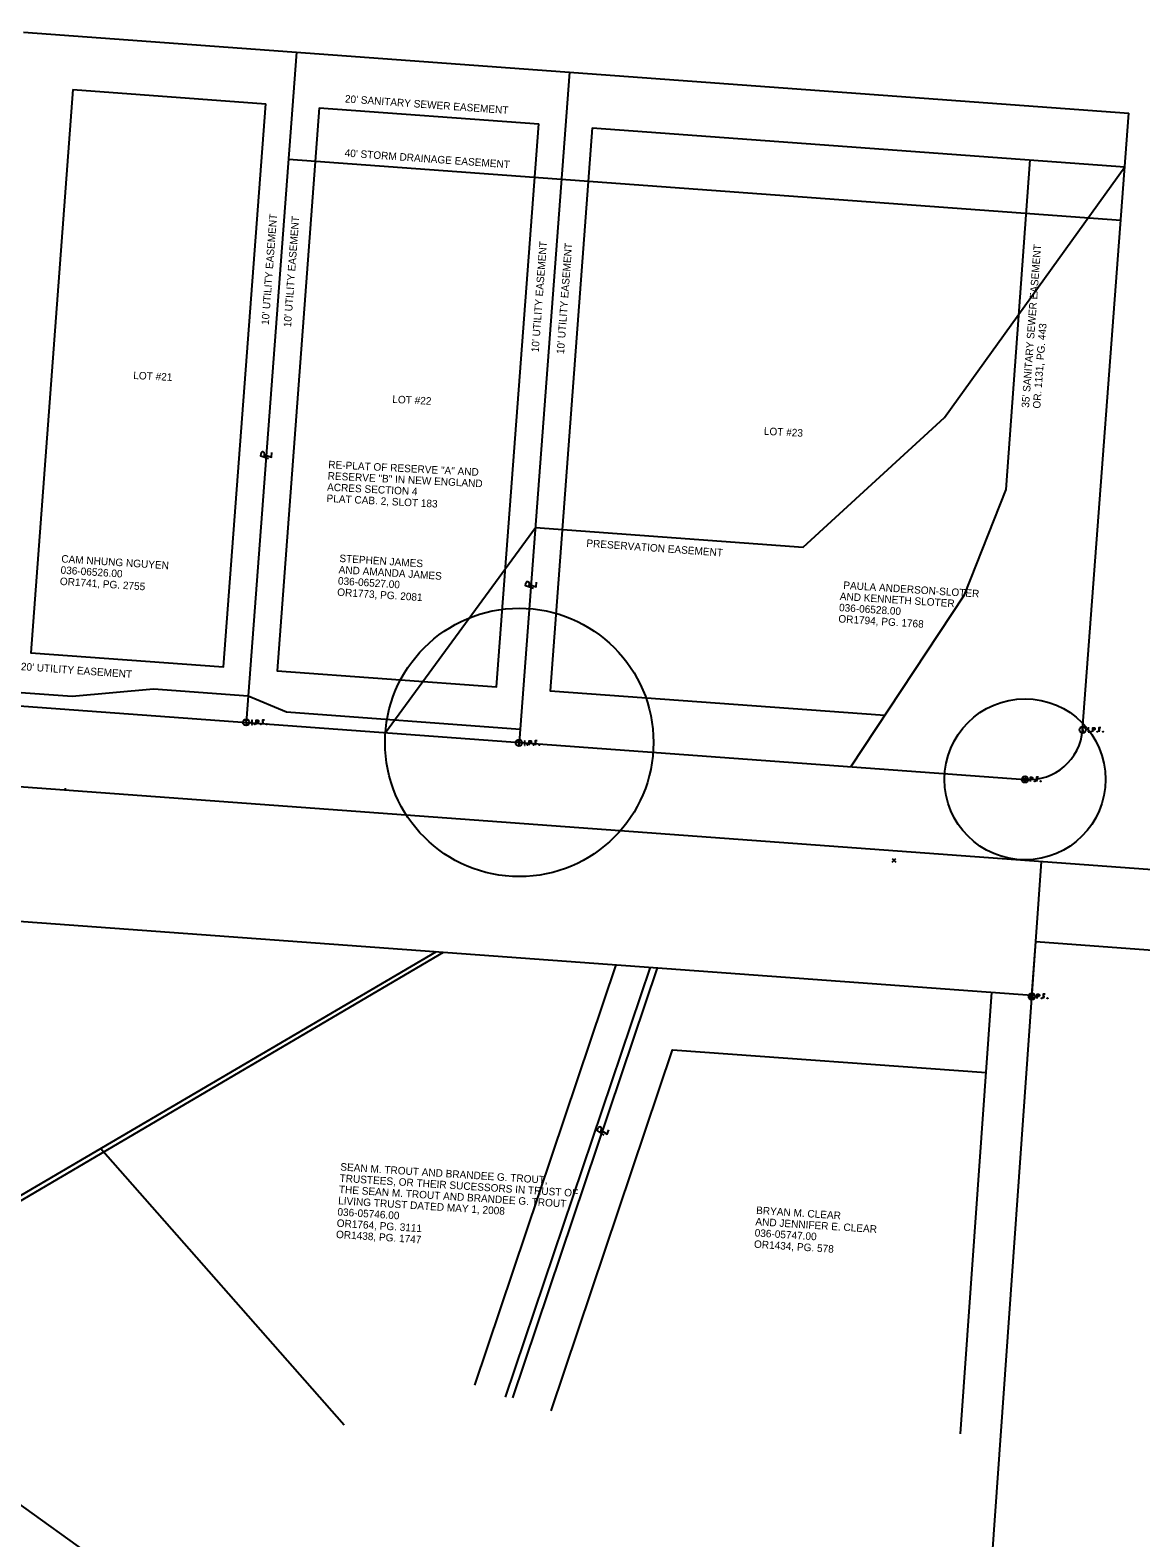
# Model space of a CAD drawing. Extents: x 1898254 to 1901377, y 701554 to 704886.
# Drawn here: x 1900233 to 1900647, y 702920 to 703481 of the extents above; entities that cross this region are included whole.
import ezdxf

# ---------------------------------------------------------------- set-up
doc = ezdxf.new("R2010")
doc.units = 0
for name, color, linetype in [('_CIVIL_CONSTRUCTION', 7, 'Continuous'), ('DV_X_Property_Line', 7, 'Continuous'), ('DV_X_Text', 7, 'Continuous'), ('RW_X_CL', 7, 'Continuous'), ('RW_X_Esmt_SC', 7, 'Continuous'), ('RW_X_Esmt_SH', 7, 'Continuous'), ('RW_X_Esmt_SW', 7, 'Continuous'), ('RW_X_Esmt_U', 7, 'Continuous'), ('RW_X_Fee_RW', 7, 'Continuous'), ('SC_Scratch1', 7, 'Continuous'), ('SC_Scratch2', 7, 'Continuous'), ('SC_Scratch3', 7, 'Continuous'), ('SC_Scratch5', 7, 'Continuous'), ('SC_Scratch6', 7, 'Continuous'), ('SC_Scratch9', 7, 'Continuous'), ('SV_X_Mon_Cells_Found', 7, 'Continuous'), ('SV_X_Random_Point', 7, 'Continuous')]:
    doc.layers.add(name, color=color, linetype=linetype)

msp = doc.modelspace()

# ---------------------------------------------------------------- linework, layer by layer
at = {"layer": '_CIVIL_CONSTRUCTION'}
msp.add_lwpolyline([(1900212.15, 703230.94), (1900212.52, 703235.93), (1900249.06, 703233.26), (1900279.35, 703236.06), (1900314.63, 703233.48), (1900328.85, 703227.43), (1900415.98, 703221.06), (1900415.61, 703216.07)], dxfattribs=at)
at = {"layer": 'DV_X_Property_Line'}
for p, q in [((1900230.87, 703480.71), (1900642.66, 703450.49)), ((1900332.6, 703473.25), (1900313.88, 703223.51)), ((1900434.32, 703465.78), (1900415.61, 703216.07)), ((1900320.66, 703322.28), (1900320.75, 703323.57)), ((1900321.34, 703323.03), (1900321.34, 703323.03)), ((1900419.32, 703273.94), (1900419.42, 703275.23)), ((1900420, 703274.69), (1900420, 703274.69)), ((1900246.51, 703198.35), (1900246.57, 703199.08)), ((1900573.07, 702649.15), (1900610.16, 703171.77)), ((1900445.82, 703070.67), (1900446.23, 703071.9)), ((1900446.67, 703071.23), (1900446.67, 703071.23))]:
    msp.add_line(p, q, dxfattribs=at)
for points in [[(1900322.21, 703321.74), (1900319.31, 703322.74), (1900319.39, 703323.77)], [(1900320.4, 703323.37), (1900323.29, 703322.36), (1900323.42, 703324.1)], [(1900420.87, 703273.4), (1900417.98, 703274.4), (1900418.06, 703275.43)], [(1900419.06, 703275.03), (1900421.95, 703274.02), (1900422.08, 703275.76)], [(1900447.2, 703069.76), (1900444.63, 703071.45), (1900444.97, 703072.43)], [(1900445.84, 703071.79), (1900448.39, 703070.1), (1900448.95, 703071.75)]]:
    msp.add_lwpolyline(points, dxfattribs=at)
for centre, start, end in [((1900320.06, 703323.62), 356.1849, 167.042), ((1900418.73, 703275.28), 356.1849, 167.042), ((1900445.58, 703072.11), 341.8852, 152.7423)]:
    msp.add_arc(centre, 0.69, start, end, dxfattribs=at)
at = {"layer": 'RW_X_CL'}
msp.add_line((1899815.76, 703229.84), (1901162.17, 703131.42), dxfattribs=at)
at = {"layer": 'RW_X_Esmt_SC'}
msp.add_lwpolyline([(1900365.74, 703219.72), (1900421.6, 703296.1), (1900521.34, 703288.81), (1900574.06, 703337.18), (1900641.2, 703430.54)], dxfattribs=at)
at = {"layer": 'RW_X_Esmt_SH'}
msp.add_line((1900608.03, 703141.85), (1901159.98, 703101.5), dxfattribs=at)
at = {"layer": 'RW_X_Esmt_SW'}
for p, q in [((1900249.32, 703459.31), (1900321.13, 703454.03)), ((1900341.07, 703452.57), (1900422.85, 703446.57)), ((1900442.8, 703445.1), (1900641.2, 703430.54)), ((1900399.03, 702976.61), (1900451.69, 703133.22))]:
    msp.add_line(p, q, dxfattribs=at)
for points in [[(1900539.12, 703207.04), (1900581.45, 703271.1), (1900596.96, 703310.34), (1900605.93, 703433.13)], [(1900427.46, 702967.05), (1900472.71, 703101.6), (1900589.53, 703093.06)]]:
    msp.add_lwpolyline(points, dxfattribs=at)
at = {"layer": 'RW_X_Esmt_U'}
for p, q in [((1900329.61, 703433.36), (1900639.68, 703410.6)), ((1900579.98, 702958.41), (1900591.66, 703122.99))]:
    msp.add_line(p, q, dxfattribs=at)
for points in [[(1900249.32, 703459.31), (1900233.59, 703249.43), (1900305.4, 703244.18), (1900321.13, 703454.03)], [(1900341.07, 703452.57), (1900325.35, 703242.72), (1900407.13, 703236.74), (1900422.85, 703446.57)], [(1900442.8, 703445.1), (1900427.08, 703235.29), (1900551.76, 703226.17)]]:
    msp.add_lwpolyline(points, dxfattribs=at)
at = {"layer": 'RW_X_Fee_RW'}
for p, q in [((1900625.5, 703220.75), (1900642.66, 703450.49)), ((1899817.89, 703259.76), (1900604.1, 703202.29)), ((1899868.13, 703175.88), (1900606.62, 703121.9)), ((1900606.62, 703121.9), (1900608.03, 703141.85))]:
    msp.add_line(p, q, dxfattribs=at)
msp.add_arc((1900605.56, 703222.24), 20, 265.8192, 355.7289, dxfattribs=at)
at = {"layer": 'SC_Scratch1'}
msp.add_circle((1900604.03, 703202.3), 30, dxfattribs=at)
at = {"layer": 'SC_Scratch2'}
msp.add_circle((1899815.76, 703229.84), 1561.35, dxfattribs=at)
at = {"layer": 'SC_Scratch3'}
msp.add_circle((1900415.61, 703216.07), 50, dxfattribs=at)
at = {"layer": 'SC_Scratch5'}
for p, q in [((1900625.5, 703220.75), (1900642.66, 703450.49)), ((1899817.89, 703259.76), (1900604.1, 703202.29)), ((1899868.13, 703175.88), (1900606.62, 703121.9)), ((1900606.62, 703121.9), (1900608.03, 703141.85)), ((1900608.03, 703141.85), (1901159.98, 703101.5))]:
    msp.add_line(p, q, dxfattribs=at)
msp.add_lwpolyline([(1900212.15, 703230.94), (1900212.52, 703235.93), (1900249.06, 703233.26), (1900279.35, 703236.06), (1900314.63, 703233.48), (1900328.85, 703227.43), (1900415.98, 703221.06), (1900415.61, 703216.07)], dxfattribs=at)
msp.add_arc((1900605.56, 703222.24), 20, 265.8192, 355.7289, dxfattribs=at)
at = {"layer": 'SC_Scratch6'}
for p, q in [((1900144.84, 702995.46), (1900387.35, 703137.92)), ((1900413.24, 702971.83), (1900467.13, 703132.09))]:
    msp.add_line(p, q, dxfattribs=at)
at = {"layer": 'SC_Scratch9'}
for p, q in [((1900141.16, 702995.38), (1900384.72, 703138.12)), ((1900410.45, 702972.08), (1900464.51, 703132.28)), ((1900350.32, 702961.74), (1900259.61, 703064.8)), ((1900141.16, 702995.38), (1900324.05, 702864.31))]:
    msp.add_line(p, q, dxfattribs=at)
at = {"layer": 'SV_X_Mon_Cells_Found'}
for p, q in [((1900313.87, 703223.67), (1900313.87, 703222.79)), ((1900625.51, 703220.87), (1900625.51, 703219.99)), ((1900415.48, 703216.01), (1900415.48, 703215.13))]:
    msp.add_line(p, q, dxfattribs=at)
for points in [[(1900315.9, 703224.36), (1900316.25, 703224.36)], [(1900315.9, 703222.76), (1900316.25, 703222.76)], [(1900316.07, 703222.76), (1900316.07, 703224.36)], [(1900317.03, 703222.97), (1900317.09, 703222.97), (1900317.12, 703222.95), (1900317.15, 703222.9), (1900317.15, 703222.83), (1900317.12, 703222.78), (1900317.09, 703222.76), (1900317.03, 703222.76), (1900317, 703222.78), (1900316.97, 703222.83), (1900316.97, 703222.9), (1900317, 703222.95), (1900317.03, 703222.97)], [(1900317.64, 703222.76), (1900317.64, 703224.36), (1900318.17, 703224.36), (1900318.22, 703224.34), (1900318.3, 703224.32), (1900318.33, 703224.29), (1900318.37, 703224.27), (1900318.41, 703224.21), (1900318.44, 703224.14), (1900318.46, 703224.04), (1900318.46, 703223.89), (1900318.45, 703223.84), (1900318.43, 703223.76), (1900318.39, 703223.68), (1900318.34, 703223.64), (1900318.31, 703223.61), (1900318.25, 703223.59), (1900318.17, 703223.58), (1900317.64, 703223.58)], [(1900319.28, 703222.97), (1900319.34, 703222.97), (1900319.37, 703222.95), (1900319.4, 703222.9), (1900319.4, 703222.83), (1900319.37, 703222.78), (1900319.34, 703222.76), (1900319.28, 703222.76), (1900319.25, 703222.78), (1900319.21, 703222.83), (1900319.21, 703222.9), (1900319.25, 703222.95), (1900319.28, 703222.97)], [(1900320.65, 703224.36), (1900319.89, 703224.36), (1900319.89, 703222.76)], [(1900319.89, 703223.58), (1900320.43, 703223.58)], [(1900321.43, 703222.97), (1900321.48, 703222.97), (1900321.52, 703222.95), (1900321.55, 703222.9), (1900321.55, 703222.83), (1900321.52, 703222.78), (1900321.48, 703222.76), (1900321.43, 703222.76), (1900321.4, 703222.78), (1900321.36, 703222.83), (1900321.36, 703222.9), (1900321.4, 703222.95), (1900321.43, 703222.97)], [(1900627.54, 703221.56), (1900627.89, 703221.56)], [(1900627.71, 703219.96), (1900627.71, 703221.56)], [(1900629.28, 703219.96), (1900629.28, 703221.56), (1900629.81, 703221.56), (1900629.86, 703221.54), (1900629.94, 703221.52), (1900629.97, 703221.49), (1900630, 703221.47), (1900630.05, 703221.4), (1900630.08, 703221.34), (1900630.1, 703221.24), (1900630.1, 703221.09), (1900630.09, 703221.04), (1900630.07, 703220.96), (1900630.03, 703220.88), (1900629.98, 703220.84), (1900629.95, 703220.81), (1900629.89, 703220.79), (1900629.81, 703220.78), (1900629.28, 703220.78)], [(1900632.29, 703221.56), (1900631.53, 703221.56), (1900631.53, 703219.96)], [(1900631.53, 703220.78), (1900632.07, 703220.78)], [(1900417.51, 703216.69), (1900417.86, 703216.69)], [(1900417.51, 703215.09), (1900417.86, 703215.09)], [(1900417.68, 703215.09), (1900417.68, 703216.69)], [(1900418.64, 703215.31), (1900418.7, 703215.31), (1900418.73, 703215.28), (1900418.76, 703215.23), (1900418.76, 703215.17), (1900418.73, 703215.12), (1900418.7, 703215.09), (1900418.64, 703215.09), (1900418.61, 703215.12), (1900418.58, 703215.17), (1900418.58, 703215.23), (1900418.61, 703215.28), (1900418.64, 703215.31)], [(1900419.25, 703215.09), (1900419.25, 703216.69), (1900419.78, 703216.69), (1900419.83, 703216.68), (1900419.91, 703216.66), (1900419.94, 703216.63), (1900419.98, 703216.61), (1900420.02, 703216.54), (1900420.05, 703216.48), (1900420.08, 703216.38), (1900420.08, 703216.23), (1900420.06, 703216.18), (1900420.04, 703216.1), (1900420, 703216.01), (1900419.95, 703215.98), (1900419.92, 703215.95), (1900419.87, 703215.93), (1900419.78, 703215.91), (1900419.25, 703215.91)], [(1900420.89, 703215.31), (1900420.95, 703215.31), (1900420.98, 703215.28), (1900421.01, 703215.23), (1900421.01, 703215.17), (1900420.98, 703215.12), (1900420.95, 703215.09), (1900420.89, 703215.09), (1900420.86, 703215.12), (1900420.83, 703215.17), (1900420.83, 703215.23), (1900420.86, 703215.28), (1900420.89, 703215.31)], [(1900422.26, 703216.69), (1900421.5, 703216.69), (1900421.5, 703215.09)], [(1900421.5, 703215.91), (1900422.04, 703215.91)], [(1900423.04, 703215.31), (1900423.1, 703215.31), (1900423.13, 703215.28), (1900423.16, 703215.23), (1900423.16, 703215.17), (1900423.13, 703215.12), (1900423.1, 703215.09), (1900423.04, 703215.09), (1900423.01, 703215.12), (1900422.98, 703215.17), (1900422.98, 703215.23), (1900423.01, 703215.28), (1900423.04, 703215.31)], [(1900627.54, 703219.96), (1900627.89, 703219.96)], [(1900628.67, 703220.17), (1900628.73, 703220.17), (1900628.76, 703220.15), (1900628.79, 703220.09), (1900628.79, 703220.03), (1900628.76, 703219.98), (1900628.73, 703219.96), (1900628.67, 703219.96), (1900628.64, 703219.98), (1900628.61, 703220.03), (1900628.61, 703220.09), (1900628.64, 703220.15), (1900628.67, 703220.17)], [(1900630.92, 703220.17), (1900630.97, 703220.17), (1900631.01, 703220.15), (1900631.04, 703220.09), (1900631.04, 703220.03), (1900631.01, 703219.98), (1900630.97, 703219.96), (1900630.92, 703219.96), (1900630.89, 703219.98), (1900630.85, 703220.03), (1900630.85, 703220.09), (1900630.89, 703220.15), (1900630.92, 703220.17)], [(1900633.07, 703220.17), (1900633.12, 703220.17), (1900633.16, 703220.15), (1900633.19, 703220.09), (1900633.19, 703220.03), (1900633.16, 703219.98), (1900633.12, 703219.96), (1900633.07, 703219.96), (1900633.04, 703219.98), (1900633, 703220.03), (1900633, 703220.09), (1900633.04, 703220.15), (1900633.07, 703220.17)], [(1900606.02, 703201.5), (1900606.02, 703203.1), (1900606.55, 703203.1), (1900606.61, 703203.09), (1900606.68, 703203.06), (1900606.72, 703203.03), (1900606.75, 703203.01), (1900606.8, 703202.95), (1900606.83, 703202.88), (1900606.85, 703202.78), (1900606.85, 703202.63), (1900606.84, 703202.58), (1900606.82, 703202.51), (1900606.77, 703202.42), (1900606.73, 703202.38), (1900606.7, 703202.35), (1900606.64, 703202.33), (1900606.55, 703202.32), (1900606.02, 703202.32)], [(1900607.67, 703201.71), (1900607.72, 703201.71), (1900607.75, 703201.69), (1900607.79, 703201.64), (1900607.79, 703201.57), (1900607.75, 703201.52), (1900607.72, 703201.5), (1900607.67, 703201.5), (1900607.63, 703201.52), (1900607.6, 703201.57), (1900607.6, 703201.64), (1900607.63, 703201.69), (1900607.67, 703201.71)], [(1900609.03, 703203.1), (1900608.27, 703203.1), (1900608.27, 703201.5)], [(1900608.27, 703202.32), (1900608.81, 703202.32)], [(1900609.82, 703201.71), (1900609.87, 703201.71), (1900609.9, 703201.69), (1900609.94, 703201.64), (1900609.94, 703201.57), (1900609.9, 703201.52), (1900609.87, 703201.5), (1900609.82, 703201.5), (1900609.78, 703201.52), (1900609.75, 703201.57), (1900609.75, 703201.64), (1900609.78, 703201.69), (1900609.82, 703201.71)], [(1900608.58, 703120.64), (1900608.58, 703122.24), (1900609.11, 703122.24), (1900609.17, 703122.23), (1900609.24, 703122.2), (1900609.28, 703122.18), (1900609.31, 703122.15), (1900609.35, 703122.09), (1900609.39, 703122.03), (1900609.41, 703121.93), (1900609.41, 703121.78), (1900609.4, 703121.73), (1900609.38, 703121.65), (1900609.33, 703121.56), (1900609.29, 703121.52), (1900609.26, 703121.5), (1900609.2, 703121.47), (1900609.11, 703121.46), (1900608.58, 703121.46)], [(1900610.23, 703120.86), (1900610.28, 703120.86), (1900610.31, 703120.83), (1900610.35, 703120.78), (1900610.35, 703120.72), (1900610.31, 703120.67), (1900610.28, 703120.64), (1900610.23, 703120.64), (1900610.19, 703120.67), (1900610.16, 703120.72), (1900610.16, 703120.78), (1900610.19, 703120.83), (1900610.23, 703120.86)], [(1900611.59, 703122.24), (1900610.83, 703122.24), (1900610.83, 703120.64)], [(1900610.83, 703121.46), (1900611.37, 703121.46)], [(1900612.37, 703120.86), (1900612.43, 703120.86), (1900612.46, 703120.83), (1900612.5, 703120.78), (1900612.5, 703120.72), (1900612.46, 703120.67), (1900612.43, 703120.64), (1900612.37, 703120.64), (1900612.34, 703120.67), (1900612.31, 703120.72), (1900612.31, 703120.78), (1900612.34, 703120.83), (1900612.37, 703120.86)]]:
    msp.add_lwpolyline(points, dxfattribs=at)
for centre, radius in [((1900313.87, 703223.56), 1.2), ((1900313.87, 703224.21), 0.16), ((1900625.51, 703220.76), 1.2), ((1900625.51, 703221.41), 0.16), ((1900415.48, 703215.89), 1.2), ((1900415.48, 703216.55), 0.16), ((1900604.03, 703202.3), 1.2), ((1900604.03, 703202.3), 0.495), ((1900606.59, 703121.44), 1.2), ((1900606.59, 703121.44), 0.495)]:
    msp.add_circle(centre, radius, dxfattribs=at)
at = {"layer": 'SV_X_Random_Point'}
for p, q in [((1900554.59, 703171.44), (1900555.92, 703172.77)), ((1900554.59, 703172.77), (1900555.92, 703171.44))]:
    msp.add_line(p, q, dxfattribs=at)

# ---------------------------------------------------------------- texts
at = {"layer": 'DV_X_Text'}
for s, rotation, p in [("20' SANITARY SEWER EASEMENT", 355.9325, (1900350.57, 703454.54)), ("40' STORM DRAINAGE EASEMENT", 355.9325, (1900350.48, 703434.37)), ("10' UTILITY EASEMENT", 85.7139, (1900322.29, 703371.55)), ("10' UTILITY EASEMENT", 85.7139, (1900330.57, 703370.68)), ("10' UTILITY EASEMENT", 85.7139, (1900422.85, 703361.34)), ("10' UTILITY EASEMENT", 85.7139, (1900432.27, 703360.67)), ("35' SANITARY SEWER EASEMENT", 85.7139, (1900605.51, 703340.69)), ('OR. 1131, PG. 443', 85.7139, (1900609.7, 703340.38)), ('LOT #21', 357.0949, (1900271.74, 703351.49)), ('LOT #22', 357.0949, (1900368.26, 703342.59)), ('LOT #23', 357.0949, (1900506.68, 703330.7)), ('RESERVE "B" IN NEW ENGLAND', 357.0949, (1900344.17, 703314.05)), ('RE-PLAT OF RESERVE "A" AND', 357.0949, (1900344.39, 703318.25)), ('ACRES SECTION 4', 357.0949, (1900343.96, 703309.86)), ('PLAT CAB. 2, SLOT 183', 357.0949, (1900343.75, 703305.67)), ('PRESERVATION EASEMENT', 355.9325, (1900440.54, 703288.97)), ('CAM NHUNG NGUYEN ', 356.3351, (1900244.92, 703283.15)), ('STEPHEN JAMES ', 356.3351, (1900348.52, 703283.31)), ('OR1741, PG. 2755', 356.3351, (1900244.38, 703274.77)), ('036-06526.00', 356.3351, (1900244.65, 703278.96)), ('036-06527.00', 356.3351, (1900347.98, 703274.93)), ('AND AMANDA JAMES', 356.3351, (1900348.25, 703279.12)), ('OR1773, PG. 2081', 356.3351, (1900347.71, 703270.74)), ('AND KENNETH SLOTER', 356.3351, (1900534.95, 703269.19)), (' PAULA ANDERSON-SLOTER ', 356.3351, (1900535.22, 703273.38)), ('036-06528.00', 356.3351, (1900534.68, 703265)), ('OR1794, PG. 1768', 356.3351, (1900534.42, 703260.81)), ("20' UTILITY EASEMENT", 355.9325, (1900229.85, 703243.02)), ('SEAN M. TROUT AND BRANDEE G. TROUT, ', 356.3351, (1900348.87, 703056.59)), ('TRUSTEES, OR THEIR SUCESSORS IN TRUST OF ', 356.3351, (1900348.6, 703052.4)), ('LIVING TRUST DATED MAY 1, 2008', 356.3351, (1900348.06, 703044.02)), ('THE SEAN M. TROUT AND BRANDEE G. TROUT ', 356.3351, (1900348.33, 703048.21)), ('036-05746.00', 356.3351, (1900347.8, 703039.83)), ('BRYAN M. CLEAR', 356.3351, (1900503.79, 703040.4)), ('OR1764, PG. 3111 ', 356.3351, (1900347.53, 703035.64)), ('036-05747.00', 356.3351, (1900503.25, 703032.02)), ('AND JENNIFER E. CLEAR', 356.3351, (1900503.52, 703036.21)), ('OR1438, PG. 1747', 356.3351, (1900347.26, 703031.45)), ('OR1434, PG. 578', 356.3351, (1900502.99, 703027.82))]:
    msp.add_text(s, height=2.8, rotation=rotation, dxfattribs=at).set_placement(p)

doc.saveas('drawing.dxf')
